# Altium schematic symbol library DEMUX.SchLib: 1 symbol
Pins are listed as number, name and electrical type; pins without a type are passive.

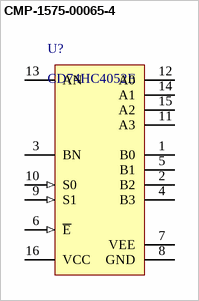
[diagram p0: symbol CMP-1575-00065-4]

## CMP-1575-00065-4
designator U?, comment CD74HC4052E
High Speed CMOS Differential 4-Channel Analog Multiplexer/Demultiplexer, N0016A, TUBE; Manufacturer: Texas Instruments; Ron(Max)(Ohms): 130; Ron(Typ)(Ohms): 45; Bandwidth(Max)(MHz): 185; VCC(Min)(V): 2; Configuration: 2 X 1：4 MUX; VCC(Max)(V): 6; Rating: Catalog; Crosstalk: Yes
footprint N0016A (DIP, 16-Leads, Body 19.7x6.6mm, Pitch 2.54mm)
pins: 1 B0, 2 B2, 3 BN, 4 B3, 5 B1, 6 ~{E} (in), 7 VEE (power), 8 GND (power), 9 S1 (in), 10 S0 (in), 11 A3, 12 A0, 13 AN, 14 A1, 15 A2, 16 VCC (power)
